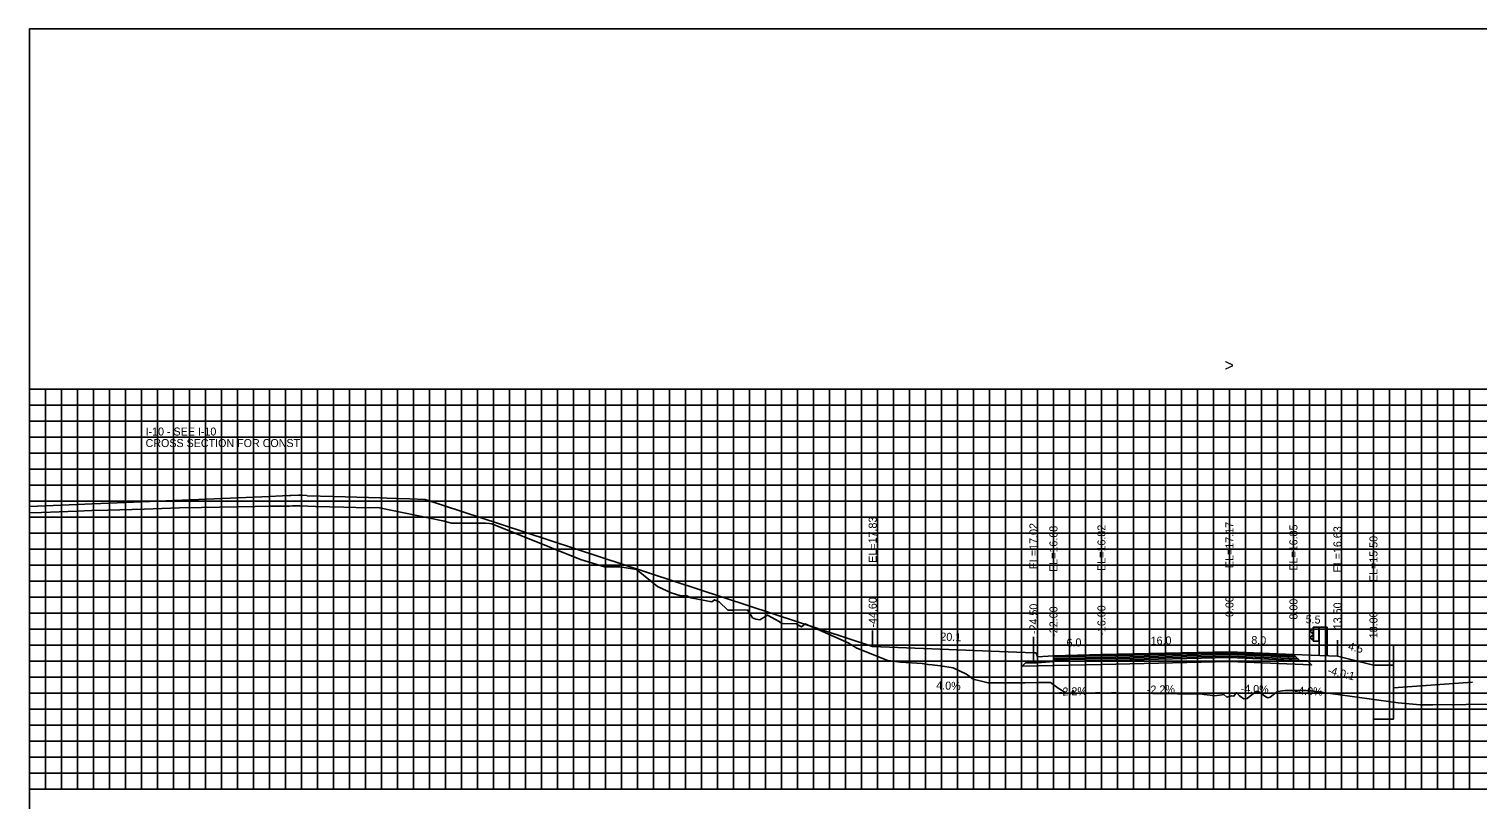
# Model space of a CAD drawing. Extents: x 1797652 to 1804145, y 245981 to 250269.
# Drawn here: x 1802480.9 to 1802661.9, y 250173.2 to 250269.4 of the extents above; entities that cross this region are included whole.
import ezdxf

# ---------------------------------------------------------------- set-up
doc = ezdxf.new("R2010")
doc.units = 0
for name, color, linetype in [('3', 7, 'Continuous'), ('4', 7, 'Continuous'), ('60', 7, 'Continuous'), ('BASE', 7, 'Continuous'), ('CL-CNST', 7, 'Continuous'), ('Level 1', 7, 'Continuous'), ('Level 62', 7, 'Continuous'), ('LOWER BINDER', 7, 'Continuous'), ('M-ROADS', 7, 'Continuous'), ('UPPER BINDER', 7, 'Continuous'), ('WEARING', 7, 'Continuous')]:
    doc.layers.add(name, color=color, linetype=linetype)

msp = doc.modelspace()

# ---------------------------------------------------------------- linework, layer by layer
for p, q in [((1802586.4, 250192.26), (1802586.4, 250194.26)), ((1802606.5, 250191.46), (1802606.5, 250193.46)), ((1802609, 250191.12), (1802609, 250193.12)), ((1802615, 250191.25), (1802615, 250193.25)), ((1802631, 250191.6), (1802631, 250193.6)), ((1802639, 250191.28), (1802639, 250193.28)), ((1802644.5, 250191.06), (1802644.5, 250193.06)), ((1802649, 250189.93), (1802649, 250191.93))]:
    msp.add_line(p, q)
for points in [[(1802481, 250079.43), (1802781, 250079.43), (1802781, 250269.43), (1802481, 250269.43)], [(1802609, 250191.12), (1802607, 250190.96), (1802606.83, 250191.46), (1802606.5, 250191.46), (1802606.5, 250190.23), (1802607, 250190.23), (1802609, 250190.4)]]:
    msp.add_lwpolyline(points, close=True)
at = {"layer": '3'}
msp.add_line((1802661.39, 250187.81), (1802651.5, 250187.11), dxfattribs=at)
at = {"layer": '60'}
for p, q in [((1802480.94, 250224.43), (1802481, 250224.43)), ((1802481, 250174.43), (1802481, 250224.43)), ((1802480.94, 250214.43), (1802481, 250214.43)), ((1802480.94, 250204.43), (1802481, 250204.43)), ((1802480.94, 250194.43), (1802481, 250194.43)), ((1802480.94, 250184.43), (1802481, 250184.43)), ((1802480.94, 250174.43), (1802481, 250174.43)), ((1802481, 250174.43), (1802781, 250174.43)), ((1802481, 250174.37), (1802481, 250174.43)), ((1802491, 250174.37), (1802491, 250174.43)), ((1802501, 250174.37), (1802501, 250174.43)), ((1802511, 250174.37), (1802511, 250174.43)), ((1802521, 250174.37), (1802521, 250174.43)), ((1802531, 250174.37), (1802531, 250174.43)), ((1802541, 250174.37), (1802541, 250174.43)), ((1802551, 250174.37), (1802551, 250174.43)), ((1802561, 250174.37), (1802561, 250174.43)), ((1802571, 250174.37), (1802571, 250174.43)), ((1802581, 250174.37), (1802581, 250174.43)), ((1802591, 250174.37), (1802591, 250174.43)), ((1802601, 250174.37), (1802601, 250174.43)), ((1802611, 250174.37), (1802611, 250174.43)), ((1802621, 250174.37), (1802621, 250174.43)), ((1802631, 250174.37), (1802631, 250174.43)), ((1802641, 250174.37), (1802641, 250174.43)), ((1802651, 250174.37), (1802651, 250174.43)), ((1802661, 250174.37), (1802661, 250174.43))]:
    msp.add_line(p, q, dxfattribs=at)
at = {"layer": 'BASE'}
msp.add_lwpolyline([(1802609, 250190.4), (1802615, 250190.53), (1802631, 250190.88), (1802639.75, 250190.53), (1802640.75, 250190.49), (1802641.27, 250189.97), (1802631, 250190.38), (1802615, 250190.03), (1802609, 250189.9), (1802605.09, 250189.81), (1802605.5, 250190.21), (1802606.5, 250190.23), (1802607, 250190.23)], close=True, dxfattribs=at)
at = {"layer": 'CL-CNST'}
for points in [[(1802481, 250209.75), (1802487.92, 250210.04), (1802488.82, 250210.08), (1802489.93, 250210.13), (1802501.15, 250210.61), (1802510.06, 250210.99), (1802513.49, 250211.14), (1802513.68, 250211.15), (1802514.65, 250211.19), (1802514.97, 250211.17), (1802515.66, 250211.15), (1802515.68, 250211.13), (1802515.72, 250211.09), (1802518.99, 250211.01), (1802524.85, 250210.86), (1802525.71, 250210.82), (1802526.89, 250210.77), (1802528.49, 250210.71), (1802530.47, 250210.62), (1802539.87, 250207.54), (1802586.4, 250192.26)], [(1802586.4, 250192.26), (1802606.5, 250191.46), (1802606.83, 250191.46), (1802607, 250190.96), (1802609, 250191.12), (1802615, 250191.25), (1802631, 250191.6), (1802639, 250191.28), (1802644.5, 250191.06), (1802649, 250189.93)]]:
    msp.add_lwpolyline(points, dxfattribs=at)
for points in [[(1802651.5, 250189.93), (1802649, 250189.93), (1802649, 250192.43), (1802651.5, 250192.43)], [(1802649, 250183.18), (1802651.5, 250183.18), (1802651.5, 250189.93), (1802649, 250189.93)]]:
    msp.add_lwpolyline(points, close=True, dxfattribs=at)
at = {"layer": 'Level 1'}
for p, q in [((1802641.46, 250194.53), (1802641.1, 250194.23)), ((1802641.1, 250194.16), (1802641.46, 250193.87)), ((1802641.46, 250193.73), (1802641.1, 250193.43)), ((1802641.1, 250193.36), (1802641.46, 250193.08)), ((1802641.46, 250194.68), (1802641.46, 250192.93)), ((1802643.21, 250194.68), (1802641.46, 250194.68)), ((1802641.51, 250194.68), (1802641.51, 250192.93)), ((1802642.16, 250194.68), (1802642.16, 250192.93)), ((1802642.21, 250194.68), (1802642.21, 250191.15)), ((1802643.21, 250194.68), (1802643.21, 250191.11)), ((1802642.21, 250192.93), (1802641.46, 250192.93))]:
    msp.add_line(p, q, dxfattribs=at)
for centre in [(1802641.13, 250194.19), (1802641.13, 250193.4)]:
    msp.add_arc(centre, 0.05, 135, 226.6208, dxfattribs=at)
at = {"layer": 'Level 62'}
for p, q in [((1802481, 250224.43), (1802781, 250224.43)), ((1802481, 250174.43), (1802481, 250224.43)), ((1802483, 250174.43), (1802483, 250224.43)), ((1802485, 250174.43), (1802485, 250224.43)), ((1802487, 250174.43), (1802487, 250224.43)), ((1802489, 250174.43), (1802489, 250224.43)), ((1802491, 250174.43), (1802491, 250224.43)), ((1802493, 250174.43), (1802493, 250224.43)), ((1802495, 250174.43), (1802495, 250224.43)), ((1802497, 250174.43), (1802497, 250224.43)), ((1802499, 250174.43), (1802499, 250224.43)), ((1802501, 250174.43), (1802501, 250224.43)), ((1802503, 250174.43), (1802503, 250224.43)), ((1802505, 250174.43), (1802505, 250224.43)), ((1802507, 250174.43), (1802507, 250224.43)), ((1802509, 250174.43), (1802509, 250224.43)), ((1802511, 250174.43), (1802511, 250224.43)), ((1802513, 250174.43), (1802513, 250224.43)), ((1802515, 250174.43), (1802515, 250224.43)), ((1802517, 250174.43), (1802517, 250224.43)), ((1802519, 250174.43), (1802519, 250224.43)), ((1802521, 250174.43), (1802521, 250224.43)), ((1802523, 250174.43), (1802523, 250224.43)), ((1802525, 250174.43), (1802525, 250224.43)), ((1802527, 250174.43), (1802527, 250224.43)), ((1802529, 250174.43), (1802529, 250224.43)), ((1802531, 250174.43), (1802531, 250224.43)), ((1802533, 250174.43), (1802533, 250224.43)), ((1802535, 250174.43), (1802535, 250224.43)), ((1802537, 250174.43), (1802537, 250224.43)), ((1802539, 250174.43), (1802539, 250224.43)), ((1802541, 250174.43), (1802541, 250224.43)), ((1802543, 250174.43), (1802543, 250224.43)), ((1802545, 250174.43), (1802545, 250224.43)), ((1802547, 250174.43), (1802547, 250224.43)), ((1802549, 250174.43), (1802549, 250224.43)), ((1802551, 250174.43), (1802551, 250224.43)), ((1802553, 250174.43), (1802553, 250224.43)), ((1802555, 250174.43), (1802555, 250224.43)), ((1802557, 250174.43), (1802557, 250224.43)), ((1802559, 250174.43), (1802559, 250224.43)), ((1802561, 250174.43), (1802561, 250224.43)), ((1802563, 250174.43), (1802563, 250224.43)), ((1802565, 250174.43), (1802565, 250224.43)), ((1802567, 250174.43), (1802567, 250224.43)), ((1802569, 250174.43), (1802569, 250224.43)), ((1802571, 250174.43), (1802571, 250224.43)), ((1802573, 250174.43), (1802573, 250224.43)), ((1802575, 250174.43), (1802575, 250224.43)), ((1802577, 250174.43), (1802577, 250224.43)), ((1802579, 250174.43), (1802579, 250224.43)), ((1802581, 250174.43), (1802581, 250224.43)), ((1802583, 250174.43), (1802583, 250224.43)), ((1802585, 250174.43), (1802585, 250224.43)), ((1802587, 250174.43), (1802587, 250224.43)), ((1802589, 250174.43), (1802589, 250224.43)), ((1802591, 250174.43), (1802591, 250224.43)), ((1802593, 250174.43), (1802593, 250224.43)), ((1802595, 250174.43), (1802595, 250224.43)), ((1802597, 250174.43), (1802597, 250224.43)), ((1802599, 250174.43), (1802599, 250224.43)), ((1802601, 250174.43), (1802601, 250224.43)), ((1802603, 250174.43), (1802603, 250224.43)), ((1802605, 250174.43), (1802605, 250224.43)), ((1802607, 250174.43), (1802607, 250224.43)), ((1802609, 250174.43), (1802609, 250224.43)), ((1802611, 250174.43), (1802611, 250224.43)), ((1802613, 250174.43), (1802613, 250224.43)), ((1802615, 250174.43), (1802615, 250224.43)), ((1802617, 250174.43), (1802617, 250224.43)), ((1802619, 250174.43), (1802619, 250224.43)), ((1802621, 250174.43), (1802621, 250224.43)), ((1802623, 250174.43), (1802623, 250224.43)), ((1802625, 250174.43), (1802625, 250224.43)), ((1802627, 250174.43), (1802627, 250224.43)), ((1802629, 250174.43), (1802629, 250224.43)), ((1802631, 250174.43), (1802631, 250224.43)), ((1802633, 250174.43), (1802633, 250224.43)), ((1802635, 250174.43), (1802635, 250224.43)), ((1802637, 250174.43), (1802637, 250224.43)), ((1802639, 250174.43), (1802639, 250224.43)), ((1802641, 250174.43), (1802641, 250224.43)), ((1802643, 250174.43), (1802643, 250224.43)), ((1802645, 250174.43), (1802645, 250224.43)), ((1802647, 250174.43), (1802647, 250224.43)), ((1802649, 250174.43), (1802649, 250224.43)), ((1802651, 250174.43), (1802651, 250224.43)), ((1802653, 250174.43), (1802653, 250224.43)), ((1802655, 250174.43), (1802655, 250224.43)), ((1802657, 250174.43), (1802657, 250224.43)), ((1802659, 250174.43), (1802659, 250224.43)), ((1802661, 250174.43), (1802661, 250224.43)), ((1802481, 250222.43), (1802781, 250222.43)), ((1802481, 250220.43), (1802781, 250220.43)), ((1802481, 250218.43), (1802781, 250218.43)), ((1802481, 250216.43), (1802781, 250216.43)), ((1802481, 250214.43), (1802781, 250214.43)), ((1802481, 250212.43), (1802781, 250212.43)), ((1802481, 250210.43), (1802781, 250210.43)), ((1802481, 250208.43), (1802781, 250208.43)), ((1802481, 250206.43), (1802781, 250206.43)), ((1802481, 250204.43), (1802781, 250204.43)), ((1802481, 250202.43), (1802781, 250202.43)), ((1802481, 250200.43), (1802781, 250200.43)), ((1802481, 250198.43), (1802781, 250198.43)), ((1802481, 250196.43), (1802781, 250196.43)), ((1802481, 250194.43), (1802781, 250194.43)), ((1802481, 250192.43), (1802781, 250192.43)), ((1802481, 250190.43), (1802781, 250190.43)), ((1802481, 250188.43), (1802781, 250188.43)), ((1802481, 250186.43), (1802781, 250186.43)), ((1802481, 250184.43), (1802781, 250184.43)), ((1802481, 250182.43), (1802781, 250182.43)), ((1802481, 250180.43), (1802781, 250180.43)), ((1802481, 250178.43), (1802781, 250178.43)), ((1802481, 250176.43), (1802781, 250176.43)), ((1802481, 250174.43), (1802781, 250174.43))]:
    msp.add_line(p, q, dxfattribs=at)
at = {"layer": 'LOWER BINDER'}
for points in [[(1802615, 250190.91), (1802631, 250191.26), (1802639.36, 250190.93), (1802639.55, 250190.73), (1802631, 250191.07), (1802615, 250190.72), (1802609, 250190.59), (1802609, 250190.78)], [(1802615, 250190.72), (1802631, 250191.07), (1802639.55, 250190.73), (1802639.75, 250190.53), (1802631, 250190.88), (1802615, 250190.53), (1802609, 250190.4), (1802609, 250190.59)]]:
    msp.add_lwpolyline(points, close=True, dxfattribs=at)
at = {"layer": 'M-ROADS'}
msp.add_lwpolyline([(1802481, 250208.99), (1802482.49, 250209.03), (1802486.91, 250209.18), (1802488.82, 250209.25), (1802490.8, 250209.31), (1802495.36, 250209.45), (1802499.74, 250209.58), (1802502.49, 250209.63), (1802509.23, 250209.76), (1802511.06, 250209.8), (1802511.82, 250209.81), (1802512.17, 250209.81), (1802513.51, 250209.82), (1802513.87, 250209.83), (1802514.78, 250209.83), (1802516.77, 250209.77), (1802520.32, 250209.67), (1802523.33, 250209.58), (1802524.55, 250209.62), (1802532.66, 250207.96), (1802533.12, 250207.85), (1802533.74, 250207.7), (1802535.81, 250207.7), (1802538.01, 250207.7), (1802538.52, 250207.62), (1802538.78, 250207.58), (1802549.88, 250203.16), (1802552.88, 250202.22), (1802553.8, 250202.22), (1802554.78, 250202.22), (1802556.89, 250201.91), (1802559.49, 250199.78), (1802561.21, 250198.98), (1802562.43, 250198.58), (1802563.19, 250198.58), (1802563.67, 250198.35), (1802566.29, 250197.86), (1802566.65, 250198.12), (1802567.2, 250197.86), (1802568.29, 250196.81), (1802568.89, 250196.82), (1802570.74, 250196.86), (1802571.4, 250195.86), (1802571.78, 250195.69), (1802572.31, 250195.61), (1802573.26, 250196.19), (1802574.73, 250195.41), (1802574.96, 250195.19), (1802575.07, 250195.16), (1802576.82, 250195.1), (1802577.5, 250194.73), (1802577.98, 250195.12), (1802583.35, 250192.74), (1802584.44, 250192.08), (1802588.29, 250190.54), (1802589.89, 250190.32), (1802592.61, 250190.15), (1802593.33, 250190), (1802593.82, 250189.99), (1802594.9, 250189.85), (1802596.48, 250189.59), (1802598.12, 250188.82), (1802598.96, 250188.17), (1802600.83, 250187.72), (1802602.24, 250187.72), (1802603.75, 250187.72), (1802605.45, 250187.74), (1802607.13, 250187.76), (1802608.65, 250187.76), (1802609.61, 250187.07), (1802610.54, 250186.46), (1802611.26, 250186.41), (1802611.45, 250186.77), (1802611.65, 250186.42), (1802612.68, 250186.43), (1802613.02, 250186.44), (1802613.78, 250186.45), (1802614.27, 250186.46), (1802614.8, 250186.49), (1802615.54, 250186.45), (1802616.27, 250186.47), (1802616.79, 250186.48), (1802618.34, 250186.45), (1802627.59, 250186.3), (1802627.85, 250186.29), (1802628.59, 250186.18), (1802629.11, 250186.11), (1802630.08, 250186.22), (1802630.3, 250186.26), (1802630.66, 250185.94), (1802631.27, 250186.11), (1802631.55, 250186.08), (1802631.88, 250186.51), (1802632.21, 250186.15), (1802632.53, 250185.91), (1802632.8, 250185.74), (1802633.22, 250185.78), (1802633.46, 250185.96), (1802634.35, 250186.64), (1802634.53, 250186.67), (1802635.54, 250185.96), (1802635.78, 250185.84), (1802636.1, 250185.95), (1802637.01, 250186.66), (1802637.95, 250186.76), (1802638, 250186.78), (1802638.22, 250186.77), (1802638.39, 250186.79), (1802640.6, 250186.79), (1802640.95, 250186.74), (1802641.2, 250186.72), (1802652.11, 250185.23), (1802654.86, 250185), (1802655.62, 250185), (1802656.43, 250185), (1802660.61, 250185.03), (1802663.49, 250185.05)], dxfattribs=at)
at = {"layer": 'UPPER BINDER'}
msp.add_lwpolyline([(1802639.36, 250190.93), (1802639.16, 250191.12), (1802631, 250191.45), (1802615, 250191.1), (1802609, 250190.97), (1802609, 250190.78), (1802615, 250190.91), (1802631, 250191.26)], close=True, dxfattribs=at)
at = {"layer": 'WEARING'}
msp.add_lwpolyline([(1802639.16, 250191.12), (1802639, 250191.28), (1802631, 250191.6), (1802615, 250191.25), (1802609, 250191.12), (1802609, 250190.97), (1802615, 250191.1), (1802631, 250191.45)], close=True, dxfattribs=at)

# ---------------------------------------------------------------- texts
msp.add_text('-4.0:1', height=1, rotation=345.9638).set_placement((1802643.2, 250188.86))
at = {"layer": '3'}
for s, p in [('I-10 - SEE I-10', (1802495.52, 250218.63)), ('CROSS SECTION FOR CONST ', (1802495.52, 250217.19))]:
    msp.add_text(s, height=1, dxfattribs=at).set_placement(p)
for s, p in [('EL=17.83', (1802586.9, 250202.73)), ('EL=17.02', (1802607, 250201.93)), ('EL=17.17', (1802631.5, 250202.07)), ('EL=16.68', (1802609.5, 250201.59)), ('EL=16.82', (1802615.5, 250201.72)), ('EL=16.85', (1802639.5, 250201.75)), ('EL=16.63', (1802645, 250201.53)), ('EL=15.50', (1802649.5, 250200.33)), ('0.00', (1802631.5, 250195.96)), ('-44.60', (1802586.9, 250194.64)), ('-24.50', (1802607, 250193.83)), ('-22.00', (1802609.5, 250193.49)), ('-16.00', (1802615.5, 250193.63)), ('8.00', (1802639.5, 250195.64)), ('13.50', (1802645, 250194.43)), ('18.00', (1802649.5, 250193.3))]:
    msp.add_text(s, height=1, rotation=90, dxfattribs=at).set_placement(p)
at = {"layer": '4'}
for s, rotation, p in [('5.5', 357.7094, (1802640.51, 250195.19)), ('20.1', 357.7094, (1802594.85, 250193.02)), ('6.0', 1.2603, (1802610.65, 250192.25)), ('16.0', 1.2603, (1802621.16, 250192.48)), ('8.0', 357.7094, (1802633.72, 250192.59)), ('4.5', 345.9638, (1802645.77, 250191.88)), ('4.0%', 357.7094, (1802594.34, 250186.94)), ('-2.2%', 1.2603, (1802609.7, 250186.13)), ('-2.2%', 1.2603, (1802620.7, 250186.37)), ('-4.0%', 357.7094, (1802632.39, 250186.54)), ('-4.0%', 357.7094, (1802639.14, 250186.27))]:
    msp.add_text(s, height=1, rotation=rotation, dxfattribs=at).set_placement(p)
at = {"layer": '60'}
for s, height, p in [('>', 1.5, (1802630.39, 250226.68)), ('-', 0.0001, (1802481, 250174.43))]:
    msp.add_text(s, height=height, dxfattribs=at).set_placement(p)

doc.saveas('drawing.dxf')
